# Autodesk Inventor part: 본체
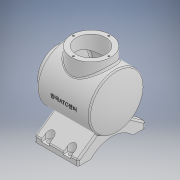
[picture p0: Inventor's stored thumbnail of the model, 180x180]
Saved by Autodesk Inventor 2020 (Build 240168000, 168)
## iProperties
Created: 2023-12
Part Number: 본체
Material: 일반
Document SubType Name: Modeling
Designer: 1강의실14
Density: 1 g/cm^3
Appearance: 기본값
Author: 1강의실14
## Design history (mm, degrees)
sketch "스케치1"
  geometry: L1 (-22.6, 0)-(135.6, 0) reference; L2 (113, 0)-(5, 0); L3 (5, 0)-(5, 50); L4 (5, 50)-(101.336, 50); A1 r 113 centre (0, 0) between (75.035, -84.491) and (75.035, 84.491); 2 further points
  constraints: 6 end point, 4 point on circle, 2 coincident, 2 horizontal, 1 centre point, 1 point on line, 1 vertical
  dimensions: "d0" = 113 radius of A1; "d1" = 108 distance of L2.start L2.end; "d2" = 50 distance of L2.end L3.end
revolve "회전1" sketch "스케치1" stored, may be unused: angle "d3" = 90 deg
sketch "스케치2"
  geometry: 1 further point
fillet "모깎기1" dims "d5" = 3
feature "쉘2" dims "d6" = 7
sketch "스케치3"
  geometry: C1 r 36 at (0, 0); 1 further point
  constraints: 1 centre point, 1 coincident
  dimensions: "d7" = 72 diameter of C1
extrude "돌출1" join sketch "스케치3" distance "d8" = 12; taper "d9" = 0 deg
sketch "스케치4"
  geometry: C1 r 36 at (0, 0) reference; 2 further points
  constraints: 1 coincident
hole "구멍1" sketch "스케치4" at (0, 0) diameter "d10" = 54; stored, may be unused: countersink angle "d14" = 90 deg, drill point angle "d16" = 0 deg; dims "d11" = 6, "d12" = 4, "d13" = 2, "d15" = 19
node "작업 평면1"
sketch "스케치5"
  geometry: L1 (7, -36)-(7, 36) reference; L2 (7, 0)-(-55, 0); C1 r 36 at (-55, 0); 1 further point
  constraints: 2 end point, 1 centre point, 1 coincident, 1 horizontal, 1 midpoint
  dimensions: "d18" = 62 distance of L2.start L2.end; "d19" = 72 diameter of C1
extrude "돌출2" join sketch "스케치5" stored distance "d20" = 12; taper "d21" = 0 deg
node "작업 평면2"
sketch "스케치7"
  geometry: L1 (0, 0)-(-77, 0); L2 (-77, 0)-(-77, 62); L3 (-77, 62)-(-67, 62); L4 (-67, 62)-(-23.587, 0); L5 (-77, 0)-(-77, 38.5); L6 (-77, 0)-(-60, 0); L7 (-60, 0)-(-60, 38.5); L8 (-60, 38.5)-(-77, 38.5); L9 (-77, 0)-(-77, -38.5); L10 (-77, -38.5)-(-60, -38.5); L11 (-60, -38.5)-(-60, 0); C1 r 43 at (0, 0) reference; C2 r 50 at (0, 0) reference; A1 r 52.096 centre (-112.096, 0) between (-77, -38.5) and (-77, 38.5); 2 further points
  constraints: 22 end point, 4 perpendicular, 4 point on line, 3 point on circle, 1 centre point, 1 horizontal, 1 vertical
  dimensions: "d31" = 77 distance of L1.start L1.end; "d32" = 62 distance of L1.end L2.end; "d33" = 10 distance of L2.end L3.end; "d34" = 55 deg angle of L3 L4; "d35" = 38.5 distance of L1.end L5.end; "d36" = 17 distance of L1.end L6.end; "d37" = 38.5 distance of L1.end L9.end; "d38" = 17 distance of L9.end L10.end
extrude "돌출3" join sketch "스케치7" distance "d39" = 80; taper "d40" = 0 deg
sketch "스케치8"
  geometry: C1 r 36 at (0, 0) reference; 2 further points
  constraints: 1 coincident
hole "구멍2" sketch "스케치8" at (0, 0) diameter "d41" = 54; stored, may be unused: countersink angle "d45" = 90 deg, drill point angle "d47" = 0 deg; dims "d42" = 6, "d43" = 4, "d44" = 2, "d46" = 40
sketch "스케치10"
  geometry: 1 further point
node "작업 평면3"
sketch "스케치11"
  geometry: L1 (-13, 62)-(-93, 62) reference; L2 (-93, 62)-(-93, 54); L3 (-93, 62)-(-73, 62); L4 (-73, 62)-(-73, 54); L5 (-80, 54)-(-80, 75.736); L6 (-66, 54)-(-66, 75.736); L7 (-66, 75.736)-(-80, 75.736); A1 r 7 centre (-73, 54) between (-80, 54) and (-66, 54); 5 further points; 2 other entities
  constraints: 12 end point, 2 point on circle, 2 tangent, 2 vertical, 1 centre point, 1 coincident, 1 horizontal, 1 perpendicular, 1 point on line, 3 other
  dimensions: "d59" = 8 distance of L1.end L2.end; "d60" = 20 distance of L1.end L3.end; "d61" = 8 distance of L3.end L4.end; "d62" = 14 diameter of A1; "d63" = 21.7361 distance of L6.start L6.end
extrude "돌출4" cut sketch "스케치11" distance "d64" = 16; taper "d65" = 0 deg
sketch "스케치12"
  geometry: A1 r 7 centre (73, -54) between (80, -54) and (66, -54) reference; 2 further points
  constraints: 1 coincident
hole "구멍3" sketch "스케치12" at (73, -54) diameter "d66" = 9; stored, may be unused: countersink angle "d70" = 90 deg, drill point angle "d72" = 0 deg; dims "d67" = 6, "d68" = 4, "d69" = 2, "d71" = 6
fillet "모깎기5" dims "d82" = 3
sketch "스케치13"
  geometry: L1 (0, 0)-(0, 32.5)
  constraints: 2 end point, 1 vertical
  dimensions: "d83" = 32.5 distance of L1.start L1.end
hole "구멍4" sketch "스케치13" at (0, 32.5) diameter "d84" = 3.242; stored, may be unused: countersink angle "d88" = 90 deg, drill point angle "d90" = 118 deg; dims "d85" = 8, "d86" = 4, "d87" = 2, "d89" = 10
sketch "스케치14"
  geometry: L1 (0, 0)-(0, 32.5); C1 r 36 at (0, 0) reference; 1 further point
  constraints: 2 end point, 1 vertical
  dimensions: "d95" = 32.5 distance of L1.start L1.end
hole "구멍5" sketch "스케치14" at (0, 32.5) diameter "d96" = 3.242; stored, may be unused: countersink angle "d100" = 90 deg, drill point angle "d102" = 118 deg; dims "d97" = 8, "d98" = 4, "d99" = 2, "d101" = 10
fillet "모깎기6" dims "d106" = 3
fillet "모깎기9" dims "d109" = 3
fillet "모깎기10" dims "d110" = 3
fillet "모깎기11" dims "d111" = 3
fillet "모깎기12" dims "d112" = 3
fillet "모깎기13" dims "d113" = 3
fillet "모깎기14" dims "d114" = 3
node "작업 평면4"
sketch "스케치15"
  geometry: L1 (-7, 36)-(-7, -36) reference; L2 (113, 0)-(0, 0); A1 r 113 centre (0, 0) between (102.166, -48.282) and (102.166, 48.282) reference; 1 further point
  constraints: 2 end point, 1 horizontal, 1 point on circle, 1 point on line, 1 other
  dimensions: "d116" = 62 distance from line of L1 point (55, 0)
feature "엠보싱1" sketch "스케치15" dims "d7" = 72, "d117" = 0.5, "d118" = 0
fillet "모깎기18" dims "d122" = 3
fillet "모깎기19" dims "d123" = 3
feature "분할1"
node "솔리드1"
mirror "미러1"
pattern_linear "직사각형 패턴1" dims "d75" = 40
mirror "미러2"
pattern_linear "직사각형 패턴2" dims "d78" = 40
pattern_circular "원형 패턴1" dims angle "d92" = 360 deg
pattern_circular "원형 패턴2" dims angle "d104" = 360 deg
feature "A9D066F2-1C7D-4E18-AEED-F7BC21143FA4" dims "d10" = 54, "d11" = 6, "d12" = 4, "d13" = 2, "d14" = 90 deg, "d15" = 19, "d16" = 0
other parameters: "d17" = 65, "d27" = 13, "d57" = -55, "d115" = 65
